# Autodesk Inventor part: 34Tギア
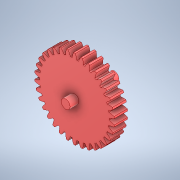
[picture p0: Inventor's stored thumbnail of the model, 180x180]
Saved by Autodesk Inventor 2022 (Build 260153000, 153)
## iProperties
CustomPartVersion: 1
Created: 2024-10
Part Number: 34Tギア
Material: アセタール樹脂、白
Document SubType Name: Modeling
Designer: jsat7
Categories: <?xml version="1.0" encoding="UTF-16"?> <MemberInstance><Categories><FamilyTemplate><FamilyTemplateParameter ValueType="xs:double" Id="1" ObjectReferenceKey="da
Density: 1.425 g/cm^3
Appearance: 滑らか - 白
Author: jsat7
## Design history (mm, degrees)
sketch "Sketch1"
  geometry: C1 r 9 at (0, 0)
  constraints: 1 centre point
  dimensions: "d0" = 18 diameter of C1 (= da_da)
extrude "Extrusion1" new body sketch "Sketch1" distance "d1" = 3 (= da_b); taper "d2" = 0 deg
workplane "Work Plane2"
sketch "Sketch2"
  geometry: C1 r 9 at (0, 0) reference; C2 r 8.5 at (0, 0)
  constraints: 1 centre point, 1 coincident
  dimensions: "d3" = 17 diameter of C2 (= da_d)
feature "ピッチ円直径" sketch "Sketch2" dims "d4" = 10, "d5" = 0
workplane "Work Plane8"
workplane "Work Plane9"
feature "平歯車" dims "da_b" = 3, "da_d" = 17, "da_aw" = 5.75, "da_da" = 18, "da_df" = 15.75, "da_dw" = 17, angle "da_beta" = 0 deg, "da_lefttooth" = 0, "da_righttooth" = 0
sketch "スケッチ3"
  geometry: C1 r 1 at (0, 0); 1 further point
  constraints: 1 centre point, 1 coincident
  dimensions: "d49" = 2 diameter of C1
extrude "押し出し2" join sketch "スケッチ3" distance "d50" = 2; taper "d51" = 0 deg
sketch "スケッチ4"
  geometry: C1 r 1 at (0, 0); 1 further point
  constraints: 1 centre point, 1 coincident
  dimensions: "d52" = 2 diameter of C1
extrude "押し出し3" join sketch "スケッチ4" distance "d53" = 6; taper "d54" = 0 deg
body "Solid1"
body "Srf1"
other parameters: "d16" = 5.75 (= da_aw), "d17" = 0, "d34" = 0.924 (computed from da_z), "d39" = 0, "d41" = 0, "d43" = 5.75 (= da_aw), "d46" = 5.75 (= da_aw), "d47" = 0, "d48" = 0
